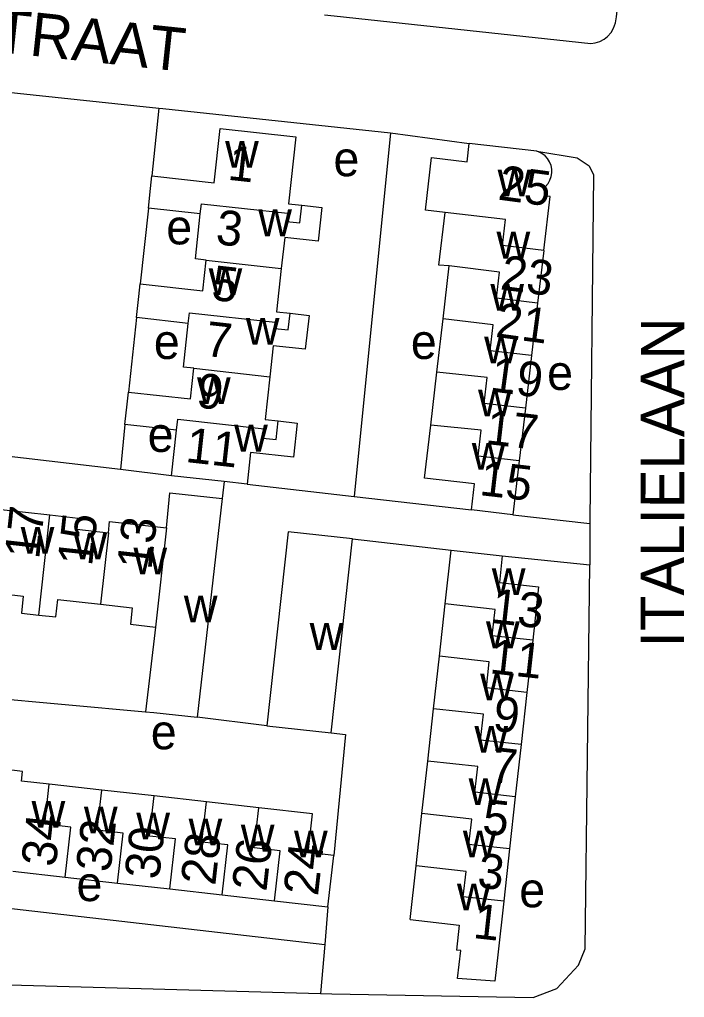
# Model space of a CAD drawing. Extents: x 161936 to 163647, y 386450 to 388633.
# Drawn here: x 162834.6 to 162911, y 388097.2 to 388209.6 of the extents above; entities that cross this region are included whole.
import ezdxf

# ---------------------------------------------------------------- set-up
doc = ezdxf.new("R2010")
doc.units = 0
for name, color, linetype in [('BLT_Basislijn', 7, 'Continuous'), ('BLT_Bebouwing', 7, 'Continuous'), ('BLT_Centroide', 7, 'Continuous'), ('BLT_Huisnummer', 7, 'Continuous'), ('BLT_Huisnummer_ tussenligend', 7, 'Continuous'), ('BLT_Onderverdeling_panden', 7, 'Continuous'), ('BLT_Straatnaam', 7, 'Continuous')]:
    doc.layers.add(name, color=color, linetype=linetype)

msp = doc.modelspace()

# ---------------------------------------------------------------- linework, layer by layer
at = {"layer": 'BLT_Basislijn'}
for p, q in [((162850.59, 388199.39), (162849.81, 388191.59)), ((162877.23, 388196.52), (162873.04, 388154.76)), ((162877.23, 388196.52), (162886.27, 388195.3)), ((162849.4, 388187.89), (162848.46, 388179.17)), ((162848.03, 388175.3), (162847.12, 388166.74)), ((162846.71, 388163.02), (162846.19, 388157.83)), ((162846.19, 388157.83), (162824.16, 388160.44)), ((162852.07, 388157.13), (162846.19, 388157.83)), ((162858.1, 388156.46), (162857.89, 388154.52)), ((162860.74, 388156.17), (162873.04, 388154.76)), ((162873.04, 388154.76), (162886.54, 388153.2)), ((162891.29, 388152.65), (162900.14, 388151.66)), ((162900.14, 388151.66), (162900.14, 388146.9)), ((162872.87, 388149.87), (162884.19, 388148.58)), ((162890.06, 388147.93), (162900.14, 388146.9)), ((162863, 388128.39), (162855, 388129.39)), ((162870.04, 388107.6), (162869.67, 388103.28)), ((162869.67, 388103.28), (162869.17, 388097.64)), ((162806.73, 388099.37), (162869.17, 388097.64))]:
    msp.add_line(p, q, dxfattribs=at)
for points in [[(162869.65, 388210.1), (162870.77, 388209.98), (162900.24, 388206.82), (162900.76, 388206.89), (162901.26, 388207.05), (162901.77, 388207.31), (162902.15, 388207.62), (162902.57, 388208.08), (162902.86, 388208.55), (162903.08, 388209.19), (162903.19, 388209.86), (162906.41, 388238.31)], [(162828.74, 388201.68), (162829.27, 388201.62), (162850.59, 388199.39)], [(162850.59, 388199.39), (162851.06, 388199.34), (162877.23, 388196.52)], [(162894.04, 388194.42), (162898.68, 388193.67), (162900.06, 388192.75), (162900.54, 388191.7), (162900.14, 388152.03), (162900.14, 388151.66)], [(162869.17, 388097.64), (162870.47, 388097.6), (162893.6, 388097.18), (162896.34, 388098.2), (162898.82, 388100.89), (162899.58, 388102.78), (162900.14, 388146.9)], [(162820.76, 388132.55), (162821.33, 388132.53), (162849.09, 388130)], [(162870.39, 388127.57), (162872.04, 388127.39), (162870.71, 388113.48)], [(162818.52, 388112.08), (162818.32, 388109.16), (162869.67, 388103.28)]]:
    msp.add_lwpolyline(points, dxfattribs=at)
at = {"layer": 'BLT_Bebouwing'}
for p, q in [((162894.04, 388194.42), (162886.27, 388195.3)), ((162894.24, 388194.35), (162894.23, 388194.35)), ((162849.65, 388190.14), (162849.81, 388191.59)), ((162849.4, 388187.89), (162849.65, 388190.14)), ((162894.84, 388183.02), (162894.13, 388176.98)), ((162864.68, 388180.96), (162864.12, 388175.98)), ((162883.27, 388175.15), (162883.98, 388181.25)), ((162848.3, 388177.72), (162848.46, 388179.17)), ((162848.03, 388175.3), (162848.3, 388177.72)), ((162894.13, 388176.98), (162893.43, 388170.93)), ((162882.56, 388169.05), (162883.27, 388175.15)), ((162893.43, 388170.93), (162892.72, 388164.89)), ((162863.36, 388168.51), (162862.82, 388163.59)), ((162881.85, 388162.96), (162882.56, 388169.05)), ((162846.97, 388165.34), (162847.12, 388166.74)), ((162846.71, 388163.02), (162846.97, 388165.34)), ((162892.72, 388164.89), (162892.02, 388158.84)), ((162892.02, 388158.84), (162891.29, 388152.65)), ((162858.1, 388156.46), (162852.07, 388157.13)), ((162860.74, 388156.17), (162858.1, 388156.46)), ((162857.89, 388154.52), (162855, 388129.39)), ((162891.29, 388152.65), (162886.54, 388153.2)), ((162870.39, 388127.57), (162872.87, 388149.87)), ((162883.51, 388142.41), (162884.19, 388148.58)), ((162884.19, 388148.58), (162890.06, 388147.93)), ((162882.84, 388136.38), (162883.51, 388142.41)), ((162850.22, 388139.74), (162849.09, 388130)), ((162893.56, 388138.22), (162892.89, 388132.23)), ((162882.17, 388130.36), (162882.84, 388136.38)), ((162892.89, 388132.23), (162892.23, 388126.23)), ((162881.5, 388124.34), (162882.17, 388130.36)), ((162863, 388128.39), (162870.39, 388127.57)), ((162892.23, 388126.23), (162891.56, 388120.23)), ((162880.84, 388118.32), (162881.5, 388124.34)), ((162844.04, 388121.01), (162838.02, 388121.69)), ((162850.05, 388120.33), (162844.04, 388121.01)), ((162856.07, 388119.65), (162850.05, 388120.33)), ((162891.56, 388120.23), (162890.9, 388114.24)), ((162862.09, 388118.96), (162856.07, 388119.65)), ((162880.17, 388112.29), (162880.84, 388118.32)), ((162870.04, 388107.6), (162870.71, 388113.48)), ((162890.9, 388114.24), (162890.23, 388108.24)), ((162833.83, 388111.69), (162839.84, 388111.01)), ((162879.49, 388106.12), (162880.17, 388112.29)), ((162839.84, 388111.01), (162845.85, 388110.33)), ((162845.85, 388110.33), (162851.86, 388109.65)), ((162851.86, 388109.65), (162857.87, 388108.97)), ((162857.87, 388108.97), (162863.88, 388108.29)), ((162863.88, 388108.29), (162870.04, 388107.6))]:
    msp.add_line(p, q, dxfattribs=at)
for points in [[(162849.81, 388191.59), (162856.98, 388190.8), (162857.67, 388197.04), (162866.36, 388196.08), (162865.51, 388188.39)], [(162883.49, 388187.37), (162881.24, 388187.64), (162881.95, 388193.69), (162886.03, 388193.22), (162886.27, 388195.3)], [(162895.04, 388190.38), (162895.33, 388190.72), (162895.55, 388191.09), (162895.7, 388191.5), (162895.77, 388191.93), (162895.76, 388192.37), (162895.68, 388192.8), (162895.51, 388193.21), (162895.28, 388193.58), (162894.98, 388193.9), (162894.63, 388194.16), (162894.24, 388194.35), (162894.04, 388194.42)], [(162894.84, 388183.02), (162895.56, 388189.21), (162894.91, 388189.29), (162895.04, 388190.38)], [(162855.37, 388187.23), (162849.4, 388187.89)], [(162867.05, 388188.22), (162869.33, 388187.97), (162868.9, 388184.09), (162865.07, 388184.51), (162864.68, 388180.96)], [(162865.51, 388188.39), (162867.05, 388188.22)], [(162856.06, 388181.91), (162854.8, 388182.05), (162855.37, 388187.23)], [(162883.98, 388181.25), (162882.79, 388181.33), (162883.49, 388187.37)], [(162848.46, 388179.17), (162855.67, 388178.37), (162856.06, 388181.91)], [(162853.99, 388174.64), (162848.03, 388175.3)], [(162865.68, 388175.8), (162867.86, 388175.56), (162867.43, 388171.67), (162863.76, 388172.07), (162863.36, 388168.51)], [(162864.12, 388175.98), (162865.68, 388175.8)], [(162854.62, 388169.48), (162853.43, 388169.61), (162853.99, 388174.64)], [(162847.12, 388166.74), (162854.23, 388165.95), (162854.62, 388169.48)], [(162852.64, 388162.36), (162846.71, 388163.02)], [(162864.32, 388163.43), (162866.51, 388163.19), (162866.07, 388159.27), (162861.14, 388159.81), (162860.74, 388156.17)], [(162862.82, 388163.59), (162864.32, 388163.43)], [(162886.54, 388153.2), (162886.89, 388156.19), (162881.14, 388156.86), (162881.85, 388162.96)], [(162852.07, 388157.13), (162852.64, 388162.36)], [(162851.48, 388151.15), (162851.87, 388155.18), (162857.89, 388154.52)], [(162832.34, 388152.09), (162832.47, 388153.25), (162838.07, 388152.63)], [(162838.07, 388152.63), (162841.34, 388152.27), (162841.2, 388150.98), (162844.81, 388150.58)], [(162844.81, 388150.58), (162844.95, 388151.87), (162851.48, 388151.15)], [(162872.87, 388149.87), (162865.48, 388150.69), (162863, 388128.39)], [(162890.06, 388147.93), (162889.73, 388144.86), (162894.24, 388144.36), (162893.56, 388138.22)], [(162831.41, 388143.71), (162835.02, 388143.31), (162834.81, 388141.34), (162836.8, 388141.12)], [(162836.8, 388141.12), (162838.78, 388140.9), (162839, 388142.91), (162843.9, 388142.37)], [(162843.9, 388142.37), (162847.54, 388141.97), (162847.33, 388140.06), (162850.22, 388139.74)], [(162849.09, 388130), (162850.03, 388129.91), (162855, 388129.39)], [(162838.02, 388121.69), (162834.83, 388122.05), (162834.95, 388123.15), (162832.12, 388123.47), (162832, 388122.37)], [(162870.71, 388113.48), (162867.75, 388113.82), (162868.26, 388118.27), (162862.09, 388118.96)], [(162890.23, 388108.24), (162889.55, 388102.09), (162889.21, 388099.06), (162884.93, 388099.35), (162885.29, 388102.57), (162884.79, 388102.62)], [(162879.49, 388106.12), (162885.11, 388105.5), (162884.79, 388102.62)]]:
    msp.add_lwpolyline(points, dxfattribs=at)
at = {"layer": 'BLT_Onderverdeling_panden'}
for p, q in [((162856.06, 388181.91), (162864.68, 388180.96)), ((162854.62, 388169.48), (162863.36, 388168.51)), ((162836.8, 388141.12), (162838.07, 388152.63)), ((162844.81, 388150.58), (162843.9, 388142.37)), ((162851.48, 388151.15), (162850.22, 388139.74))]:
    msp.add_line(p, q, dxfattribs=at)
for points in [[(162855.37, 388187.23), (162855.5, 388188.38), (162865.39, 388187.29), (162865.29, 388186.35), (162866.82, 388186.18), (162867.05, 388188.22)], [(162894.84, 388183.02), (162890.1, 388183.57), (162890.45, 388186.56), (162883.49, 388187.37)], [(162894.13, 388176.98), (162889.4, 388177.52), (162889.74, 388180.52), (162883.98, 388181.25)], [(162853.99, 388174.64), (162854.12, 388175.86), (162863.99, 388174.77), (162863.93, 388174.05), (162865.47, 388173.88), (162865.68, 388175.8)], [(162893.43, 388170.93), (162888.69, 388171.48), (162889.04, 388174.47), (162883.27, 388175.15)], [(162892.72, 388164.89), (162887.99, 388165.43), (162888.34, 388168.43), (162882.56, 388169.05)], [(162852.64, 388162.36), (162852.79, 388163.63), (162862.7, 388162.53), (162862.55, 388161.45), (162864.08, 388161.28), (162864.32, 388163.43)], [(162892.02, 388158.84), (162887.28, 388159.39), (162887.63, 388162.38), (162881.85, 388162.96)], [(162893.56, 388138.22), (162888.9, 388138.74), (162889.24, 388141.77), (162883.51, 388142.41)], [(162892.89, 388132.23), (162888.24, 388132.74), (162888.57, 388135.75), (162882.84, 388136.38)], [(162892.23, 388126.23), (162887.57, 388126.74), (162887.9, 388129.73), (162882.17, 388130.36)], [(162891.56, 388120.23), (162886.91, 388120.75), (162887.24, 388123.7), (162881.5, 388124.34)], [(162839.84, 388111.01), (162840.49, 388116.75), (162837.5, 388117.09), (162838.02, 388121.69)], [(162845.85, 388110.33), (162846.5, 388116.07), (162843.51, 388116.41), (162844.04, 388121.01)], [(162851.86, 388109.65), (162852.51, 388115.39), (162849.53, 388115.73), (162850.05, 388120.33)], [(162857.87, 388108.97), (162858.52, 388114.71), (162855.55, 388115.04), (162856.07, 388119.65)], [(162863.88, 388108.29), (162864.53, 388114.03), (162861.57, 388114.36), (162862.09, 388118.96)], [(162890.9, 388114.24), (162886.24, 388114.75), (162886.57, 388117.68), (162880.84, 388118.32)], [(162890.23, 388108.24), (162885.58, 388108.75), (162885.9, 388111.66), (162880.17, 388112.29)]]:
    msp.add_lwpolyline(points, dxfattribs=at)

# ---------------------------------------------------------------- texts
at = {"layer": 'BLT_Centroide'}
for s, p in [('w', (162858.22, 388192.53)), ('e', (162870.67, 388191.55)), ('w', (162889.53, 388189.25)), ('w', (162862.03, 388184.66)), ('e', (162851.46, 388183.72)), ('w', (162889.41, 388182.09)), ('w', (162856.33, 388177.91)), ('w', (162888.7, 388176.09)), ('w', (162860.6, 388172.19)), ('e', (162850.03, 388170.55)), ('e', (162879.56, 388170.55)), ('w', (162887.99, 388170.03)), ('e', (162895.22, 388166.99)), ('w', (162854.99, 388165.38)), ('w', (162887.29, 388163.94)), ('e', (162849.32, 388159.87)), ('w', (162859.26, 388159.91)), ('w', (162886.57, 388157.81)), ('w', (162834.73, 388148.17)), ('w', (162840.8, 388147.53)), ('w', (162847.69, 388145.8)), ('w', (162888.87, 388143.41)), ('w', (162853.48, 388140.27)), ('w', (162867.94, 388137.12)), ('w', (162888.2, 388137.31)), ('w', (162887.53, 388131.31)), ('e', (162849.68, 388125.7)), ('w', (162886.87, 388125.31)), ('w', (162886.2, 388119.28)), ('w', (162835.98, 388116.67)), ('w', (162842, 388116.02)), ('w', (162848.02, 388115.33)), ('w', (162854.03, 388114.64)), ('w', (162860.03, 388113.95)), ('w', (162866.14, 388113.27)), ('w', (162885.54, 388113.28)), ('e', (162841.14, 388108.25)), ('w', (162884.86, 388107.19)), ('e', (162892.02, 388107.54))]:
    msp.add_text(s, height=4, dxfattribs=at).set_placement(p)
at = {"layer": 'BLT_Huisnummer'}
for s, rotation, p in [('1', 353.6971, (162858.42, 388191.16)), ('25', 352.3341, (162889.47, 388188.88)), ('5', 353.7001, (162856.55, 388177.35)), ('19', 352.3348, (162888.55, 388166.86)), ('11', 353.699, (162853.58, 388158.72)), ('15', 353.3545, (162887.35, 388154.92)), ('17', 83.6981, (162836.84, 388147.47)), ('13', 83.7006, (162849.75, 388146.25)), ('13', 353.6768, (162888.71, 388140.23)), ('9', 353.6762, (162888.88, 388127.85)), ('5', 353.6762, (162887.67, 388116.01)), ('32', 83.5448, (162845.03, 388111.48)), ('28', 83.5442, (162857.08, 388109.96)), ('24', 83.5359, (162868.88, 388108.76)), ('1', 353.6783, (162886.62, 388104.02))]:
    msp.add_text(s, height=4, rotation=rotation, dxfattribs=at).set_placement(p)
at = {"layer": 'BLT_Huisnummer_ tussenligend'}
for s, rotation, p in [('3', 353.6971, (162857.05, 388183.76)), ('23', 352.3348, (162889.73, 388178.56)), ('21', 352.3348, (162889.19, 388173.1)), ('7', 353.7001, (162855.82, 388170.92)), ('9', 353.7001, (162854.81, 388165)), ('17', 353.3545, (162888.05, 388160.8)), ('15', 83.7006, (162842.92, 388146.66)), ('11', 353.6762, (162888.53, 388134.45)), ('7', 353.6762, (162888.6, 388121.99)), ('34', 83.5448, (162838.75, 388112.1)), ('30', 83.5442, (162850.62, 388110.65)), ('26', 83.5359, (162862.96, 388109.28)), ('3', 353.6783, (162887.1, 388109.82))]:
    msp.add_text(s, height=4, rotation=rotation, dxfattribs=at).set_placement(p)
at = {"layer": 'BLT_Straatnaam'}
for s, rotation, p in [('TARANTOSTRAAT', 353.8977, (162795.37, 388209.75)), ('ITALIELAAN', 89.9302, (162910.95, 388137.41))]:
    msp.add_text(s, height=5, rotation=rotation, dxfattribs=at).set_placement(p)

doc.saveas('drawing.dxf')
